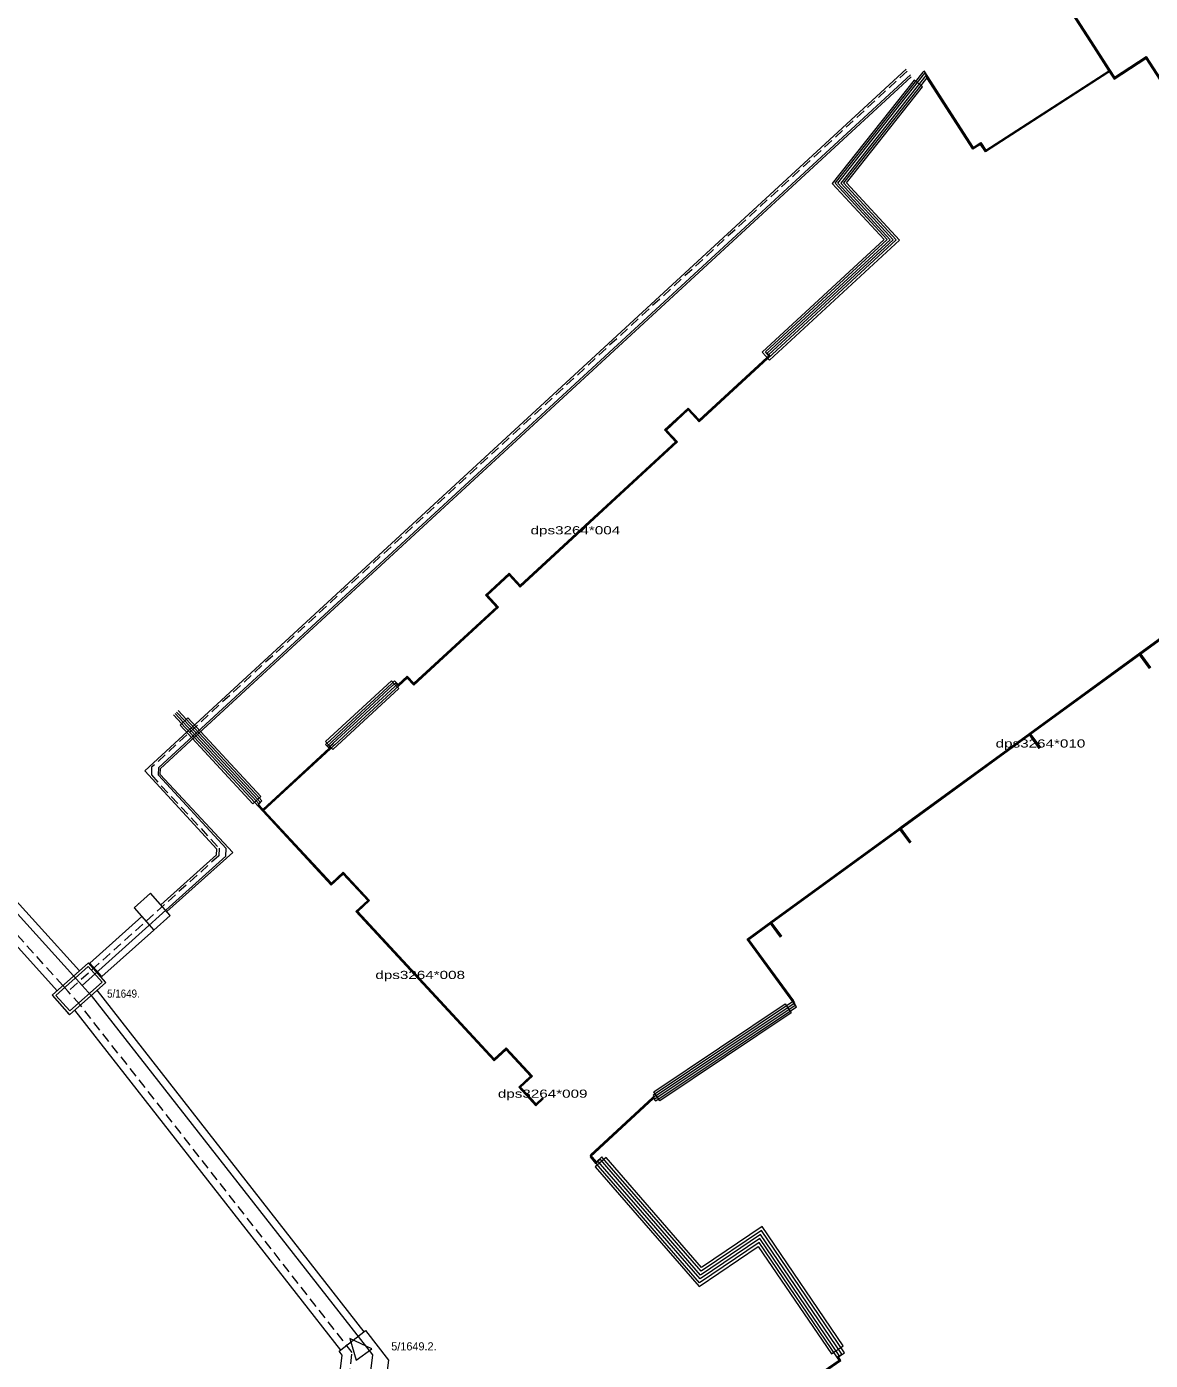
# Model space of a CAD drawing. Extents: x -473467 to -473049, y -1106745 to -1106181.
# Drawn here: x -473358.5 to -473234.1, y -1106405.6 to -1106257.8 of the extents above; entities that cross this region are included whole.
import ezdxf
from ezdxf.enums import TextEntityAlignment as Align

# ---------------------------------------------------------------- set-up
doc = ezdxf.new("R2010")
doc.units = 0
doc.header["$LTSCALE"] = 0.36
doc.linetypes.add('MEDIUM_DASHED', pattern=[4.5, 3, -1.5])
for name, color, linetype, lineweight in [('1', 7, 'MEDIUM_DASHED', 13), ('11', 7, 'Continuous', 13), ('17', 7, 'Continuous', 13), ('4', 7, 'Continuous', 13), ('7', 7, 'Continuous', 13)]:
    doc.layers.add(name, color=color, linetype=linetype, lineweight=lineweight)
doc.layers.add('19', color=7, linetype='Continuous')
doc.layers.add('6', color=7, linetype='Continuous')

msp = doc.modelspace()

# ---------------------------------------------------------------- linework, layer by layer
at = {"layer": '1', "linetype": 'Continuous'}
for points in [[(-473466.219, -1106238.046), (-473457.772, -1106247.401), (-473458.003, -1106251.921), (-473462.159, -1106255.675), (-473462.389, -1106260.194), (-473461.313, -1106261.385), (-473456.793, -1106261.615), (-473452.637, -1106257.862), (-473448.118, -1106258.092), (-473353.346, -1106363.026), (-473352.415, -1106364.072)], [(-473352.415, -1106364.072), (-473336.477, -1106349.741), (-473336.439, -1106348.899), (-473343.959, -1106340.778), (-473343.925, -1106339.932), (-473260.636, -1106263.159)], [(-473352.415, -1106364.072), (-473351.401, -1106365.177), (-473320.246, -1106405.022), (-473320.796, -1106409.514), (-473325.208, -1106412.964), (-473325.757, -1106417.456), (-473324.773, -1106418.715), (-473320.281, -1106419.265), (-473315.869, -1106415.815), (-473311.377, -1106416.365), (-473246.451, -1106499.393), (-473246.061, -1106500.236)]]:
    msp.add_lwpolyline(points, dxfattribs=at)
at = {"layer": '1'}
for points in [[(-473353.967, -1106364.728), (-473354.537, -1106364.088), (-473448.232, -1106260.345), (-473452.752, -1106260.115), (-473456.908, -1106263.868), (-473461.428, -1106263.638), (-473464.641, -1106260.08), (-473464.411, -1106255.56), (-473460.255, -1106251.807), (-473460.025, -1106247.287), (-473467.342, -1106239.185)], [(-473261.008, -1106262.755), (-473344.703, -1106339.901), (-473344.737, -1106340.748), (-473337.221, -1106348.864), (-473337.26, -1106349.705), (-473353.967, -1106364.728)], [(-473247.32, -1106501.369), (-473247.945, -1106500.085), (-473311.652, -1106418.606), (-473316.144, -1106418.057), (-473320.555, -1106421.506), (-473325.047, -1106420.956), (-473327.999, -1106417.182), (-473327.449, -1106412.69), (-473323.038, -1106409.24), (-473322.488, -1106404.748), (-473352.595, -1106366.242), (-473353.967, -1106364.728)]]:
    msp.add_lwpolyline(points, dxfattribs=at)
at = {"layer": '11'}
for points in [[(-473277.543, -1106203.475), (-473276.937, -1106203.085), (-473273.703, -1106200.999), (-473267.136, -1106211.182), (-473268.648, -1106212.157), (-473266.708, -1106215.166), (-473265.195, -1106214.19), (-473255.212, -1106229.67), (-473256.725, -1106230.646), (-473254.784, -1106233.654), (-473253.272, -1106232.679), (-473244.101, -1106246.898), (-473246.623, -1106248.524), (-473246.081, -1106249.365), (-473246.921, -1106249.907), (-473240.361, -1106260.078), (-473238.707, -1106262.643)], [(-473277.368, -1106203.303), (-473276.964, -1106203.043), (-473273.688, -1106200.93), (-473267.067, -1106211.197), (-473268.579, -1106212.172), (-473266.693, -1106215.097), (-473265.18, -1106214.121), (-473255.143, -1106229.685), (-473256.656, -1106230.661), (-473254.77, -1106233.585), (-473253.257, -1106232.61), (-473244.032, -1106246.913), (-473246.553, -1106248.539), (-473246.011, -1106249.379), (-473246.852, -1106249.921), (-473240.319, -1106260.051), (-473238.667, -1106262.612)], [(-473277.194, -1106203.132), (-473273.673, -1106200.861), (-473266.997, -1106211.211), (-473268.51, -1106212.187), (-473266.678, -1106215.028), (-473265.166, -1106214.052), (-473255.074, -1106229.7), (-473256.587, -1106230.676), (-473254.755, -1106233.516), (-473253.242, -1106232.541), (-473243.963, -1106246.928), (-473246.484, -1106248.554), (-473245.942, -1106249.394), (-473246.783, -1106249.936), (-473240.277, -1106260.024), (-473238.628, -1106262.581)], [(-473277.019, -1106202.959), (-473273.658, -1106200.792), (-473266.928, -1106211.226), (-473268.441, -1106212.202), (-473266.663, -1106214.958), (-473265.151, -1106213.983), (-473255.005, -1106229.715), (-473256.517, -1106230.691), (-473254.74, -1106233.447), (-473253.227, -1106232.471), (-473243.894, -1106246.943), (-473246.415, -1106248.569), (-473245.873, -1106249.409), (-473246.714, -1106249.951), (-473240.235, -1106259.997), (-473238.589, -1106262.55)], [(-473238.707, -1106262.643), (-473238.074, -1106263.624), (-473234.545, -1106261.347), (-473228.897, -1106270.104), (-473230.578, -1106271.188), (-473228.367, -1106274.617), (-473226.686, -1106273.533), (-473215.683, -1106290.594), (-473217.364, -1106291.678), (-473215.152, -1106295.107), (-473213.472, -1106294.023), (-473207.824, -1106302.78), (-473213.374, -1106306.359), (-473213.458, -1106306.413), (-473214.009, -1106306.769), (-473213.287, -1106307.887)], [(-473238.667, -1106262.612), (-473238.06, -1106263.555), (-473234.53, -1106261.278), (-473228.828, -1106270.119), (-473230.509, -1106271.203), (-473228.352, -1106274.548), (-473226.671, -1106273.464), (-473215.614, -1106290.609), (-473217.295, -1106291.693), (-473215.137, -1106295.038), (-473213.457, -1106293.954), (-473207.755, -1106302.795), (-473213.347, -1106306.401), (-473213.389, -1106306.428), (-473213.78, -1106306.68), (-473213.088, -1106307.753)], [(-473238.628, -1106262.581), (-473238.045, -1106263.486), (-473234.515, -1106261.209), (-473228.759, -1106270.134), (-473230.44, -1106271.218), (-473228.337, -1106274.479), (-473226.656, -1106273.395), (-473215.545, -1106290.624), (-473217.225, -1106291.708), (-473215.123, -1106294.969), (-473213.442, -1106293.885), (-473207.686, -1106302.81), (-473213.551, -1106306.592), (-473212.886, -1106307.623)], [(-473238.589, -1106262.55), (-473238.03, -1106263.416), (-473234.5, -1106261.14), (-473228.69, -1106270.149), (-473230.371, -1106271.233), (-473228.322, -1106274.41), (-473226.641, -1106273.326), (-473215.476, -1106290.639), (-473217.156, -1106291.723), (-473215.108, -1106294.9), (-473213.427, -1106293.816), (-473207.617, -1106302.825), (-473213.293, -1106306.485), (-473213.322, -1106306.504), (-473212.691, -1106307.484)], [(-473276.535, -1106294.492), (-473276.318, -1106294.292), (-473276.705, -1106293.873), (-473263.213, -1106281.42), (-473268.981, -1106275.172), (-473259.229, -1106262.851), (-473259.131, -1106262.727)], [(-473276.501, -1106294.529), (-473276.248, -1106294.295), (-473276.505, -1106294.016), (-473276.466, -1106293.979), (-473262.874, -1106281.433), (-473268.665, -1106275.16), (-473259.026, -1106262.981)], [(-473258.922, -1106263.237), (-473268.35, -1106275.148), (-473262.535, -1106281.447), (-473276.306, -1106294.158), (-473276.177, -1106294.298), (-473276.467, -1106294.566)], [(-473258.817, -1106263.492), (-473268.034, -1106275.136), (-473262.196, -1106281.46), (-473275.951, -1106294.158), (-473276.433, -1106294.603)], [(-473259.131, -1106262.727), (-473253.668, -1106271.199), (-473252.827, -1106270.657), (-473252.285, -1106271.497), (-473238.663, -1106262.712)], [(-473259.026, -1106262.981), (-473258.967, -1106263.074), (-473253.683, -1106271.268), (-473252.842, -1106270.726), (-473252.3, -1106271.566), (-473238.812, -1106262.868), (-473238.593, -1106262.727)], [(-473238.524, -1106262.742), (-473238.785, -1106262.91), (-473252.315, -1106271.636), (-473252.857, -1106270.795), (-473253.698, -1106271.337), (-473258.922, -1106263.237)], [(-473238.455, -1106262.757), (-473238.758, -1106262.952), (-473252.33, -1106271.705), (-473252.872, -1106270.864), (-473253.712, -1106271.406), (-473258.817, -1106263.492)], [(-473317.78, -1106330.312), (-473317.395, -1106330.733), (-473316.377, -1106329.793), (-473315.641, -1106330.59), (-473306.496, -1106322.149), (-473307.717, -1106320.826), (-473305.086, -1106318.398), (-473303.866, -1106319.72), (-473286.656, -1106303.835), (-473287.877, -1106302.512), (-473285.247, -1106300.084), (-473284.026, -1106301.407), (-473276.535, -1106294.492)], [(-473317.655, -1106330.524), (-473317.396, -1106330.802), (-473316.38, -1106329.864), (-473315.644, -1106330.661), (-473306.426, -1106322.151), (-473307.646, -1106320.829), (-473305.089, -1106318.468), (-473303.868, -1106319.791), (-473286.586, -1106303.838), (-473287.807, -1106302.515), (-473285.25, -1106300.155), (-473284.029, -1106301.477), (-473276.501, -1106294.529)], [(-473276.467, -1106294.566), (-473284.031, -1106301.548), (-473285.252, -1106300.225), (-473287.736, -1106302.518), (-473286.515, -1106303.841), (-473303.871, -1106319.862), (-473305.092, -1106318.539), (-473307.576, -1106320.832), (-473306.355, -1106322.154), (-473315.647, -1106330.731), (-473316.382, -1106329.934), (-473317.399, -1106330.872), (-473317.528, -1106330.734)], [(-473276.433, -1106294.603), (-473284.034, -1106301.619), (-473285.255, -1106300.296), (-473287.665, -1106302.521), (-473286.445, -1106303.844), (-473303.874, -1106319.932), (-473305.095, -1106318.61), (-473307.505, -1106320.834), (-473306.284, -1106322.157), (-473315.65, -1106330.802), (-473316.385, -1106330.005), (-473317.362, -1106330.907)], [(-473262.006, -1106346.747), (-473261.761, -1106346.568), (-473260.583, -1106348.184), (-473261.761, -1106346.568), (-473247.401, -1106336.104), (-473246.223, -1106337.72), (-473247.401, -1106336.104), (-473235.214, -1106327.223), (-473234.036, -1106328.84), (-473235.214, -1106327.223), (-473226.331, -1106320.75), (-473225.749, -1106321.547)], [(-473261.974, -1106346.785), (-473261.772, -1106346.637), (-473260.627, -1106348.212), (-473261.772, -1106346.637), (-473247.412, -1106336.173), (-473246.268, -1106337.757), (-473247.412, -1106336.173), (-473235.225, -1106327.293), (-473234.075, -1106328.867), (-473235.225, -1106327.293), (-473226.26, -1106320.76), (-473225.567, -1106321.71)], [(-473261.943, -1106346.824), (-473261.783, -1106346.707), (-473260.665, -1106348.257), (-473261.783, -1106346.707), (-473247.423, -1106336.243), (-473246.301, -1106337.796), (-473247.423, -1106336.243), (-473235.236, -1106327.363), (-473234.12, -1106328.911), (-473235.236, -1106327.363), (-473226.192, -1106320.772), (-473225.389, -1106321.873)], [(-473261.913, -1106346.865), (-473261.794, -1106346.777), (-473260.704, -1106348.284), (-473261.794, -1106346.777), (-473247.434, -1106336.313), (-473246.357, -1106337.834), (-473247.434, -1106336.313), (-473235.247, -1106327.433), (-473234.142, -1106328.961), (-473235.247, -1106327.433), (-473226.116, -1106320.779), (-473225.204, -1106322.031)], [(-473325.044, -1106337.794), (-473325.268, -1106337.551), (-473325.431, -1106337.375), (-473325.068, -1106337.04), (-473324.899, -1106336.884), (-473318.089, -1106330.598), (-473317.996, -1106330.512), (-473317.78, -1106330.312)], [(-473324.973, -1106337.796), (-473325.102, -1106337.657), (-473325.231, -1106337.517), (-473324.905, -1106337.217), (-473324.737, -1106337.061), (-473317.926, -1106330.774), (-473317.833, -1106330.688), (-473317.655, -1106330.524)], [(-473317.528, -1106330.734), (-473317.67, -1106330.864), (-473317.763, -1106330.95), (-473324.574, -1106337.237), (-473324.743, -1106337.393), (-473325.032, -1106337.66), (-473324.9, -1106337.802)], [(-473317.362, -1106330.907), (-473317.507, -1106331.041), (-473317.6, -1106331.127), (-473317.731, -1106331.248), (-473324.411, -1106337.413), (-473324.58, -1106337.569), (-473324.873, -1106337.839)], [(-473332.391, -1106344.77), (-473333.314, -1106343.775), (-473341.394, -1106335.061), (-473342.287, -1106334.099)], [(-473332.39, -1106344.703), (-473332.921, -1106344.13), (-473332.779, -1106343.998), (-473333.138, -1106343.612), (-473341.218, -1106334.898), (-473342.111, -1106333.936)], [(-473332.387, -1106344.627), (-473332.916, -1106344.057), (-473332.637, -1106343.799), (-473332.962, -1106343.449), (-473341.042, -1106334.735), (-473341.935, -1106333.772)], [(-473332.386, -1106344.555), (-473332.913, -1106343.986), (-473332.495, -1106343.599), (-473332.786, -1106343.285), (-473340.866, -1106334.572), (-473341.759, -1106333.609)], [(-473324.873, -1106337.839), (-473332.386, -1106344.775), (-473324.801, -1106352.955), (-473323.481, -1106351.731), (-473320.761, -1106354.664), (-473322.081, -1106355.888), (-473306.753, -1106372.416), (-473305.433, -1106371.192), (-473302.714, -1106374.125), (-473304.033, -1106375.349), (-473302.13, -1106377.402), (-473301.286, -1106376.619)], [(-473324.9, -1106337.802), (-473332.384, -1106344.71), (-473332.352, -1106344.744), (-473324.798, -1106352.89), (-473323.478, -1106351.666), (-473320.696, -1106354.667), (-473322.016, -1106355.891), (-473306.751, -1106372.351), (-473305.431, -1106371.127), (-473302.649, -1106374.128), (-473303.968, -1106375.352), (-473302.129, -1106377.336), (-473301.323, -1106376.588)], [(-473324.973, -1106337.796), (-473332.381, -1106344.634), (-473332.313, -1106344.707), (-473324.795, -1106352.814), (-473323.475, -1106351.59), (-473320.62, -1106354.669), (-473321.939, -1106355.893), (-473306.748, -1106372.275), (-473305.428, -1106371.051), (-473302.572, -1106374.131), (-473303.892, -1106375.355), (-473302.122, -1106377.264), (-473301.352, -1106376.55)], [(-473325.044, -1106337.794), (-473332.378, -1106344.563), (-473332.276, -1106344.673), (-473324.793, -1106352.743), (-473323.473, -1106351.519), (-473320.549, -1106354.672), (-473321.869, -1106355.896), (-473306.745, -1106372.204), (-473305.426, -1106370.98), (-473302.502, -1106374.133), (-473303.821, -1106375.357), (-473302.114, -1106377.198), (-473301.381, -1106376.518)], [(-473273.259, -1106366.45), (-473278.734, -1106358.936), (-473276.087, -1106357.007), (-473274.909, -1106358.624), (-473276.087, -1106357.007), (-473262.006, -1106346.747)], [(-473273.359, -1106366.228), (-473278.664, -1106358.947), (-473276.098, -1106357.077), (-473274.952, -1106358.649), (-473276.098, -1106357.077), (-473261.974, -1106346.785)], [(-473273.458, -1106366.006), (-473278.595, -1106358.958), (-473276.109, -1106357.147), (-473274.991, -1106358.679), (-473276.109, -1106357.147), (-473261.943, -1106346.824)], [(-473273.559, -1106365.783), (-473278.524, -1106358.969), (-473276.12, -1106357.217), (-473275.018, -1106358.715), (-473276.12, -1106357.217), (-473261.913, -1106346.865)], [(-473289.032, -1106376.323), (-473289.136, -1106376.184), (-473288.91, -1106376.033), (-473273.683, -1106365.868), (-473273.6, -1106365.812), (-473273.559, -1106365.783)], [(-473289.109, -1106376.599), (-473288.862, -1106376.866), (-473288.511, -1106376.632), (-473273.259, -1106366.45)], [(-473289.106, -1106376.533), (-473288.986, -1106376.661), (-473288.869, -1106376.583), (-473288.825, -1106376.554), (-473273.4, -1106366.256), (-473273.359, -1106366.228)], [(-473289.104, -1106376.458), (-473289.003, -1106376.384), (-473288.803, -1106376.25), (-473288.777, -1106376.233), (-473273.525, -1106366.051), (-473273.458, -1106366.006)], [(-473295.449, -1106383.819), (-473295.475, -1106383.79), (-473296.095, -1106383.077), (-473289.109, -1106376.599)], [(-473295.437, -1106383.757), (-473296.088, -1106383.008), (-473289.141, -1106376.566), (-473289.106, -1106376.533)], [(-473295.432, -1106383.687), (-473296.085, -1106382.932), (-473289.177, -1106376.526), (-473289.104, -1106376.458)], [(-473295.427, -1106383.616), (-473296.083, -1106382.862), (-473289.211, -1106376.49), (-473289.032, -1106376.323)], [(-473268.737, -1106405.222), (-473268.695, -1106405.194), (-473268.513, -1106405.07), (-473277.32, -1106392.105), (-473283.939, -1106396.601), (-473295.233, -1106383.58), (-473295.437, -1106383.757)], [(-473268.667, -1106405.235), (-473268.221, -1106404.931), (-473277.235, -1106391.661), (-473283.884, -1106396.177), (-473294.991, -1106383.371), (-473295.024, -1106383.333), (-473295.432, -1106383.687)], [(-473268.598, -1106405.248), (-473267.928, -1106404.793), (-473277.15, -1106391.216), (-473283.828, -1106395.752), (-473294.75, -1106383.161), (-473294.815, -1106383.085), (-473295.427, -1106383.616)], [(-473268.712, -1106405.347), (-473277.405, -1106392.55), (-473283.994, -1106397.026), (-473295.449, -1106383.819)], [(-473236.982, -1106452.242), (-473237.966, -1106450.574), (-473244.267, -1106454.92), (-473250.764, -1106445.499), (-473249.283, -1106444.477), (-473251.554, -1106441.184), (-473253.035, -1106442.206), (-473266.092, -1106423.275), (-473264.61, -1106422.253), (-473266.881, -1106418.96), (-473268.363, -1106419.982), (-473275.136, -1106410.16), (-473268.535, -1106405.608), (-473268.712, -1106405.347)], [(-473236.707, -1106452.078), (-473237.013, -1106451.559), (-473237.033, -1106451.527), (-473237.266, -1106451.663), (-473237.95, -1106450.503), (-473244.255, -1106454.85), (-473250.695, -1106445.512), (-473249.213, -1106444.49), (-473251.541, -1106441.115), (-473253.023, -1106442.137), (-473266.022, -1106423.287), (-473264.54, -1106422.265), (-473266.868, -1106418.89), (-473268.35, -1106419.912), (-473275.066, -1106410.173), (-473268.466, -1106405.621), (-473268.737, -1106405.222)], [(-473236.432, -1106451.914), (-473236.782, -1106451.321), (-473237.247, -1106451.596), (-473237.935, -1106450.431), (-473244.242, -1106454.781), (-473250.625, -1106445.525), (-473249.144, -1106444.503), (-473251.528, -1106441.045), (-473253.01, -1106442.067), (-473265.953, -1106423.3), (-473264.471, -1106422.278), (-473266.855, -1106418.821), (-473268.337, -1106419.843), (-473274.997, -1106410.186), (-473268.396, -1106405.634), (-473268.667, -1106405.235)], [(-473236.146, -1106451.771), (-473236.532, -1106451.116), (-473237.23, -1106451.527), (-473237.919, -1106450.359), (-473244.229, -1106454.711), (-473250.556, -1106445.537), (-473249.074, -1106444.515), (-473251.515, -1106440.976), (-473252.997, -1106441.998), (-473265.883, -1106423.313), (-473264.401, -1106422.291), (-473266.842, -1106418.751), (-473268.324, -1106419.773), (-473274.927, -1106410.199), (-473268.327, -1106405.647), (-473268.598, -1106405.248)]]:
    msp.add_lwpolyline(points, dxfattribs=at)
at = {"layer": '17'}
for points in [[(-473276.259, -1106294.768), (-473261.857, -1106281.474), (-473267.718, -1106275.124), (-473259.287, -1106264.49), (-473260.236, -1106263.737), (-473269.296, -1106275.184), (-473263.552, -1106281.406), (-473277.073, -1106293.886)], [(-473325.441, -1106337.057), (-473318.124, -1106330.303), (-473317.717, -1106330.744), (-473317.31, -1106331.185), (-473324.627, -1106337.939)], [(-473333.491, -1106343.937), (-473332.611, -1106343.121), (-473340.678, -1106334.422), (-473341.558, -1106335.238)], [(-473274.496, -1106366.121), (-473273.829, -1106367.12), (-473288.403, -1106376.849), (-473289.07, -1106375.851)], [(-473294.345, -1106383.139), (-473295.554, -1106384.187), (-473284.05, -1106397.45), (-473277.49, -1106392.994), (-473269.396, -1106404.909), (-473268.073, -1106404.01), (-473277.065, -1106390.772), (-473283.773, -1106395.328)]]:
    msp.add_lwpolyline(points, close=True, dxfattribs=at)
at = {"layer": '4'}
for points in [[(-473355.316, -1106365.184), (-473353.786, -1106366.901), (-473350.204, -1106363.707), (-473351.734, -1106361.99)], [(-473322.035, -1106405.599), (-473320.293, -1106404.332), (-473322.733, -1106403.194)]]:
    msp.add_lwpolyline(points, close=True, dxfattribs=at)
at = {"layer": '7'}
for p, q in [((-473445.744, -1106259.448), (-473352.712, -1106362.457)), ((-473448.193, -1106261.66), (-473355.174, -1106364.655)), ((-473351.443, -1106361.866), (-473351.368, -1106361.799)), ((-473350.579, -1106362.835), (-473350.504, -1106362.768)), ((-473350.766, -1106364.612), (-473321.18, -1106402.451)), ((-473353.235, -1106366.812), (-473323.779, -1106404.483))]:
    msp.add_line(p, q, dxfattribs=at)
for points in [[(-473343.704, -1106355.132), (-473337.517, -1106349.583), (-473337.489, -1106348.961), (-473345.469, -1106340.294), (-473261.1, -1106262.527)], [(-473343.039, -1106355.879), (-473335.717, -1106349.353), (-473343.765, -1106340.707), (-473343.738, -1106340.018), (-473260.549, -1106263.378)], [(-473345.777, -1106356.443), (-473351.552, -1106361.592), (-473350.221, -1106363.085), (-473344.447, -1106357.937)], [(-473354.01, -1106367.101), (-473353.811, -1106367.325), (-473349.779, -1106363.733), (-473351.709, -1106361.567), (-473355.74, -1106365.16), (-473353.811, -1106367.325)]]:
    msp.add_lwpolyline(points, dxfattribs=at)
for points in [[(-473344.834, -1106353.862), (-473346.641, -1106355.472), (-473344.447, -1106357.937), (-473342.64, -1106356.327)], [(-473323.937, -1106404.606), (-473321.022, -1106402.327), (-473318.466, -1106405.597), (-473318.93, -1106409.387), (-473324.219, -1106413.523), (-473324.663, -1106417.152), (-473324.214, -1106417.727), (-473320.585, -1106418.171), (-473315.295, -1106414.035), (-473311.505, -1106414.498), (-473308.949, -1106417.768), (-473311.864, -1106420.047), (-473312.213, -1106419.6), (-473315.838, -1106419.156), (-473321.13, -1106423.294), (-473324.92, -1106422.83), (-473329.786, -1106416.607), (-473329.323, -1106412.816), (-473324.031, -1106408.679), (-473323.587, -1106405.053)]]:
    msp.add_lwpolyline(points, close=True, dxfattribs=at)

# ---------------------------------------------------------------- texts
at = {"layer": '19', "width": 1.4}
for s, p in [('dps3264*004', (-473297.757, -1106314.082)), ('dps3264*010', (-473246.226, -1106337.708)), ('dps3264*008', (-473314.95, -1106363.357)), ('dps3264*009', (-473301.381, -1106376.518))]:
    msp.add_text(s, height=0.9, dxfattribs=at).set_placement(p, align=Align.CENTER)
at = {"layer": '6', "width": 0.9}
msp.add_text('5/1649.', height=0.9, dxfattribs=at).set_placement((-473349.639, -1106365.43))
at = {"layer": '6'}
msp.add_text('5/1649.2.', height=0.9, dxfattribs=at).set_placement((-473318.154, -1106404.519))

doc.saveas('drawing.dxf')
